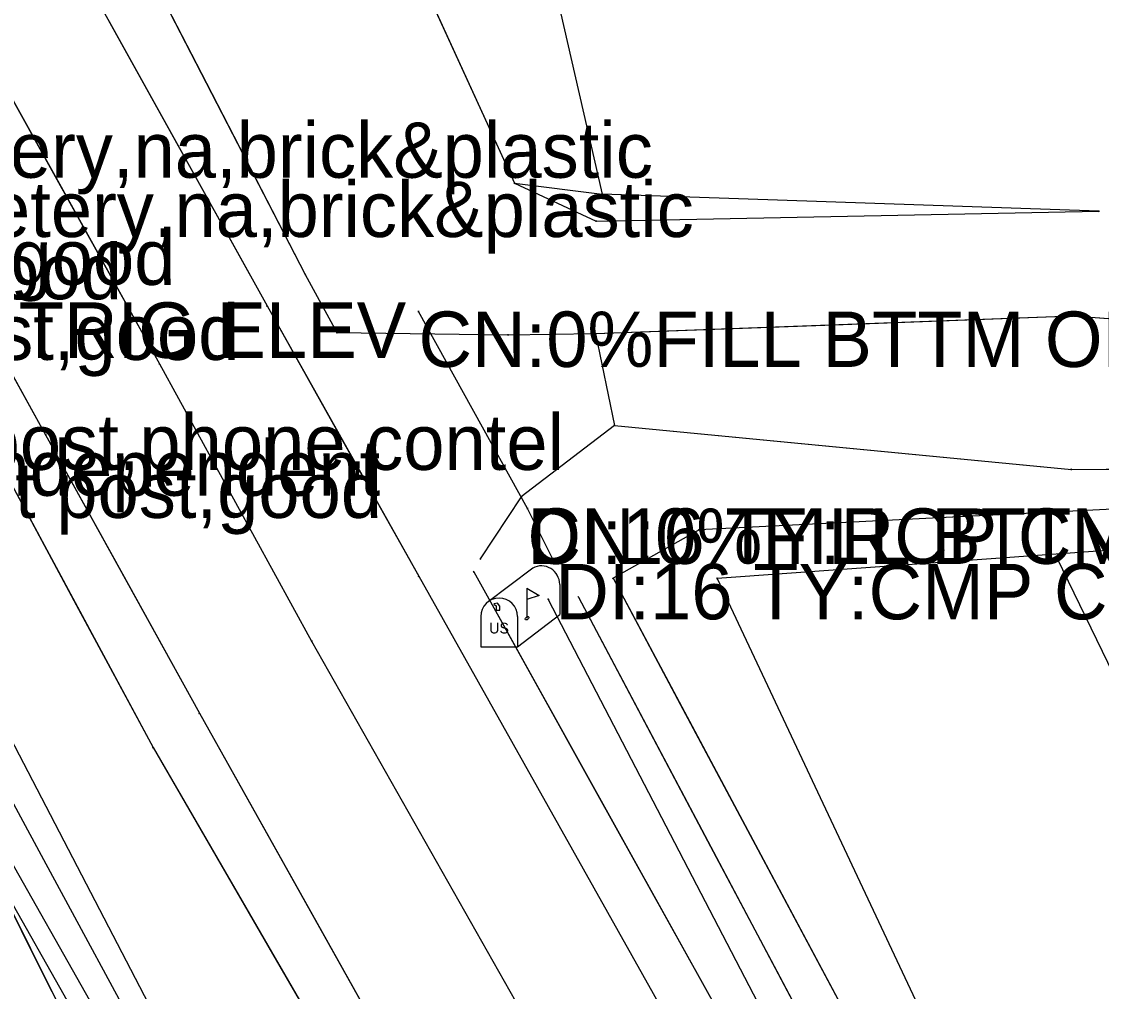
# Model space of a CAD drawing. Extents: x -99999 to 591807, y -99999 to 347168.
# Drawn here: x 589172.2 to 589269.6, y 343878.6 to 343966.1 of the extents above; entities that cross this region are included whole.
import ezdxf

# ---------------------------------------------------------------- set-up
doc = ezdxf.new("R2010")
doc.units = 0
for name, color, linetype in [('S_BREAKLINE', 7, 'Continuous'), ('S_DITCHLINE', 7, 'Continuous'), ('S_DRG_PT_SYM', 7, 'Continuous'), ('S_DRIVEWAY', 7, 'Continuous'), ('S_EDGE_BITUMINOUS', 7, 'Continuous'), ('S_EDGE_PAVEMENT', 7, 'Continuous'), ('S_FENCE', 7, 'Continuous'), ('S_FENCE_ANNOT', 7, 'Continuous'), ('S_GRD_PT_SYM', 7, 'Continuous'), ('S_MAILBOX', 7, 'Continuous'), ('S_MSC_PT_SYM', 7, 'Continuous'), ('S_PAVEMENT_CROWN', 7, 'Continuous'), ('S_RDW_PT_SYM', 7, 'Continuous'), ('S_SECONDARY_CTL_ANNOT', 7, 'Continuous'), ('S_SHOULDER', 7, 'Continuous'), ('S_SIDE_DRAIN', 7, 'Continuous'), ('S_SIDE_DRAIN_ANNOT', 7, 'Continuous'), ('S_SIGN_ANNOT', 7, 'Continuous'), ('S_TELEPHONE_UTILITIES_ANNOT', 7, 'Continuous'), ('S_UNDERGROUND_CABLE', 7, 'Continuous'), ('S_UTILITY_POLE_ANNOT', 7, 'Continuous')]:
    doc.layers.add(name, color=color, linetype=linetype)

msp = doc.modelspace()

# ---------------------------------------------------------------- linework, layer by layer
at = {"layer": 'S_BREAKLINE'}
for points in [[(589178.707, 344059.245), (589196.219, 344018.171), (589214.23, 343995.774), (589224.572, 343950.501)], [(589202.172, 343983.211), (589216.682, 343951.497)], [(589216.682, 343951.497), (589224.572, 343950.501)], [(589269.346, 343948.966), (589224.572, 343950.501)], [(589307.826, 343917.087), (589276.801, 343918.854), (589234.944, 343915.868), (589255.436, 343872.286), (589279.54, 343830.17), (589292.522, 343804.787), (589322.966, 343749.691), (589346.464, 343706.108)], [(589265.562, 343917.716), (589282.367, 343883.117), (589299.057, 343829.076), (589343.814, 343764.168), (589361.971, 343718.709)], [(589219.719, 343913.972), (589243.694, 343867.816), (589265.543, 343828.386), (589280.919, 343799.183), (589311.536, 343745.758), (589334.694, 343701.686)]]:
    msp.add_lwpolyline(points, dxfattribs=at)
at = {"layer": 'S_DITCHLINE'}
for points in [[(589292.944, 343680.411), (589286.275, 343692.355), (589279.607, 343704.3), (589272.939, 343716.245), (589266.27, 343728.189), (589258.002, 343743.462), (589249.733, 343758.735), (589241.464, 343774.007), (589233.196, 343789.28), (589223.252, 343805.716), (589213.308, 343822.151), (589203.364, 343838.587), (589193.42, 343855.022), (589183.836, 343872.755), (589174.252, 343890.487), (589164.668, 343908.22), (589155.084, 343925.952), (589144.535, 343945.213)], [(589295.448, 343681.497), (589288.727, 343693.546), (589282.007, 343705.594), (589275.286, 343717.643), (589268.565, 343729.691), (589260.423, 343745.108), (589252.281, 343760.524), (589244.139, 343775.94), (589235.997, 343791.356), (589225.751, 343807.46), (589215.504, 343823.564), (589205.258, 343839.668), (589195.011, 343855.773), (589185.737, 343873.601), (589176.463, 343891.43), (589167.19, 343909.259), (589157.916, 343927.088), (589145.699, 343945.78)], [(589307.314, 343921.098), (589276.619, 343922.409), (589233.323, 343920.25), (589225.562, 343915.881)], [(589307.314, 343921.098), (589291.967, 343921.754), (589276.619, 343922.409), (589254.971, 343921.33), (589233.323, 343920.25), (589225.562, 343915.881)], [(589225.562, 343915.881), (589249.825, 343870.459), (589271.448, 343830.318), (589284.396, 343800.855), (589316.11, 343747.232), (589340.099, 343704.207)], [(589225.562, 343915.881), (589231.628, 343904.525), (589237.694, 343893.17), (589243.759, 343881.814), (589249.825, 343870.459), (589260.637, 343850.388), (589271.448, 343830.318), (589277.922, 343815.587), (589284.396, 343800.855), (589292.324, 343787.449), (589300.253, 343774.044), (589308.181, 343760.638), (589316.11, 343747.232), (589328.104, 343725.72), (589340.099, 343704.207)], [(589222.45, 343914.182), (589246.278, 343869.207), (589268.613, 343829.634), (589282.91, 343800.448), (589312.934, 343746.223), (589336.247, 343702.575)], [(589222.45, 343914.182), (589228.407, 343902.938), (589234.364, 343891.694), (589240.321, 343880.451), (589246.278, 343869.207), (589257.445, 343849.42), (589268.613, 343829.634), (589275.761, 343815.041), (589282.91, 343800.448), (589290.416, 343786.892), (589297.922, 343773.336), (589305.428, 343759.779), (589312.934, 343746.223), (589324.591, 343724.399), (589336.247, 343702.575)]]:
    msp.add_lwpolyline(points, dxfattribs=at)
at = {"layer": 'S_DRG_PT_SYM'}
for points in [[(589208.028, 343939.931), (589208.028, 343939.981), (589208.028, 343939.931), (589207.978, 343939.931), (589208.028, 343939.931), (589208.028, 343939.881), (589208.028, 343939.931), (589208.078, 343939.931)], [(589217.839, 343922.177), (589217.839, 343922.227), (589217.839, 343922.177), (589217.789, 343922.177), (589217.839, 343922.177), (589217.839, 343922.127), (589217.839, 343922.177), (589217.889, 343922.177)], [(589217.839, 343922.177), (589217.839, 343922.227), (589217.839, 343922.177), (589217.789, 343922.177), (589217.839, 343922.177), (589217.839, 343922.127), (589217.839, 343922.177), (589217.889, 343922.177)], [(589220.361, 343917.177), (589220.361, 343917.227), (589220.361, 343917.177), (589220.311, 343917.177), (589220.361, 343917.177), (589220.361, 343917.127), (589220.361, 343917.177), (589220.411, 343917.177)]]:
    msp.add_lwpolyline(points, dxfattribs=at)
at = {"layer": 'S_DRIVEWAY'}
for points in [[(589223.97, 343937.943), (589267.021, 343939.532), (589306.29, 343936.636)], [(589223.97, 343937.943), (589245.495, 343938.737), (589267.021, 343939.532), (589286.655, 343938.084), (589306.29, 343936.636)], [(589225.702, 343929.651), (589266.882, 343925.696), (589307.69, 343926.064)], [(589225.702, 343929.651), (589246.292, 343927.673), (589266.882, 343925.696), (589287.286, 343925.88), (589307.69, 343926.064)]]:
    msp.add_lwpolyline(points, dxfattribs=at)
at = {"layer": 'S_EDGE_BITUMINOUS'}
msp.add_lwpolyline([(589200.666, 343938.024), (589216.098, 343937.819), (589223.97, 343937.943), (589225.702, 343929.651), (589217.288, 343923.216), (589213.599, 343917.633)], dxfattribs=at)
msp.add_lwpolyline([(589200.666, 343938.024), (589216.098, 343937.819), (589223.97, 343937.943), (589225.702, 343929.651), (589217.288, 343923.216), (589213.599, 343917.633)], dxfattribs=at)
at = {"layer": 'S_EDGE_PAVEMENT'}
for points in [[(589044.064, 344210.383), (589062.611, 344176.978), (589089.035, 344129.797), (589108.669, 344094.278), (589125.565, 344064.193), (589145.195, 344028.974), (589161.688, 343999.91), (589175.358, 343974.711), (589194.37, 343940.441), (589208.048, 343916.063), (589231.369, 343874.529), (589249.479, 343841.725), (589270.078, 343805.141), (589289.795, 343769.164), (589308.912, 343733.904), (589328.843, 343697.753)], [(589023.862, 344198.696), (589042.878, 344164.723), (589068.451, 344118.72), (589088.798, 344082.183), (589106.799, 344049.991), (589124.918, 344017.734), (589142.031, 343987.049), (589155.388, 343963.212), (589174.405, 343928.823), (589188.269, 343903.723), (589210.345, 343864.327), (589229.441, 343830.558), (589250.196, 343793.383), (589269.113, 343758.947), (589288.957, 343722.639), (589307.862, 343688.024)], [(589148.709, 343975.131), (589155.388, 343963.212), (589164.896, 343946.018), (589174.405, 343928.823), (589181.337, 343916.273), (589188.269, 343903.723), (589199.307, 343884.025), (589210.345, 343864.327), (589219.893, 343847.443), (589229.441, 343830.558), (589239.819, 343811.971), (589250.196, 343793.383), (589259.655, 343776.165), (589269.113, 343758.947), (589279.035, 343740.793), (589288.957, 343722.639), (589298.41, 343705.331), (589307.862, 343688.024)], [(589175.358, 343974.711), (589184.864, 343957.576), (589194.37, 343940.441), (589201.209, 343928.252), (589208.048, 343916.063), (589219.709, 343895.296), (589231.369, 343874.529), (589240.424, 343858.127), (589249.479, 343841.725), (589259.779, 343823.433), (589270.078, 343805.141), (589279.936, 343787.153), (589289.795, 343769.164), (589299.354, 343751.534), (589308.912, 343733.904), (589318.878, 343715.829), (589328.843, 343697.753)]]:
    msp.add_lwpolyline(points, dxfattribs=at)
at = {"layer": 'S_FENCE'}
for p, q in [((589202.172, 343983.211), (589216.682, 343951.497)), ((589216.682, 343951.497), (589224.037, 343948.089)), ((589224.037, 343948.089), (589269.346, 343948.966)), ((589188.108, 343852.274), (589151.217, 343926.322))]:
    msp.add_line(p, q, dxfattribs=at)
for points in [[(589202.172, 343983.211), (589216.682, 343951.497)], [(589216.682, 343951.497), (589224.037, 343948.089)], [(589224.037, 343948.089), (589269.346, 343948.966)], [(589174.979, 343878.628), (589153.096, 343922.551)]]:
    msp.add_lwpolyline(points, dxfattribs=at)
at = {"layer": 'S_GRD_PT_SYM'}
for points in [[(589216.682, 343951.497), (589216.688, 343951.547), (589216.682, 343951.497), (589216.632, 343951.504), (589216.682, 343951.497), (589216.676, 343951.448), (589216.682, 343951.497), (589216.732, 343951.491)], [(589216.682, 343951.497), (589216.727, 343951.518), (589216.682, 343951.497), (589216.661, 343951.543), (589216.682, 343951.497), (589216.637, 343951.477), (589216.682, 343951.497), (589216.703, 343951.452)], [(589224.572, 343950.501), (589224.578, 343950.551), (589224.572, 343950.501), (589224.522, 343950.508), (589224.572, 343950.501), (589224.565, 343950.452), (589224.572, 343950.501), (589224.621, 343950.495)], [(589224.572, 343950.501), (589224.57, 343950.451), (589224.572, 343950.501), (589224.622, 343950.5), (589224.572, 343950.501), (589224.573, 343950.551), (589224.572, 343950.501), (589224.522, 343950.503)], [(589224.572, 343950.501), (589224.62, 343950.513), (589224.572, 343950.501), (589224.56, 343950.55), (589224.572, 343950.501), (589224.523, 343950.49), (589224.572, 343950.501), (589224.583, 343950.453)], [(589269.346, 343948.966), (589269.346, 343949.016), (589269.346, 343948.966), (589269.296, 343948.966), (589269.346, 343948.966), (589269.346, 343948.916), (589269.346, 343948.966), (589269.396, 343948.966)], [(589269.346, 343948.966), (589269.344, 343948.916), (589269.346, 343948.966), (589269.396, 343948.965), (589269.346, 343948.966), (589269.347, 343949.016), (589269.346, 343948.966), (589269.296, 343948.968)], [(589233.323, 343920.25), (589233.348, 343920.207), (589233.323, 343920.25), (589233.367, 343920.275), (589233.323, 343920.25), (589233.299, 343920.294), (589233.323, 343920.25), (589233.28, 343920.226)], [(589265.562, 343917.716), (589265.607, 343917.738), (589265.562, 343917.716), (589265.541, 343917.761), (589265.562, 343917.716), (589265.518, 343917.694), (589265.562, 343917.716), (589265.584, 343917.671)], [(589225.562, 343915.881), (589225.606, 343915.905), (589225.562, 343915.881), (589225.538, 343915.925), (589225.562, 343915.881), (589225.518, 343915.857), (589225.562, 343915.881), (589225.585, 343915.837)], [(589225.562, 343915.881), (589225.586, 343915.837), (589225.562, 343915.881), (589225.605, 343915.906), (589225.562, 343915.881), (589225.537, 343915.925), (589225.562, 343915.881), (589225.518, 343915.856)], [(589234.944, 343915.868), (589234.99, 343915.889), (589234.944, 343915.868), (589234.923, 343915.913), (589234.944, 343915.868), (589234.899, 343915.847), (589234.944, 343915.868), (589234.966, 343915.823)], [(589219.719, 343913.972), (589219.764, 343913.995), (589219.719, 343913.972), (589219.696, 343914.016), (589219.719, 343913.972), (589219.675, 343913.949), (589219.719, 343913.972), (589219.742, 343913.927)], [(589222.45, 343914.182), (589222.495, 343914.205), (589222.45, 343914.182), (589222.427, 343914.226), (589222.45, 343914.182), (589222.406, 343914.158), (589222.45, 343914.182), (589222.474, 343914.138)]]:
    msp.add_lwpolyline(points, close=True, dxfattribs=at)
at = {"layer": 'S_MAILBOX'}
for p, q in [((589214.188, 343913.696), (589218.322, 343916.805)), ((589217.803, 343914.985), (589217.803, 343912.27)), ((589220.754, 343915.331), (589220.754, 343912.616)), ((589213.634, 343912.422), (589213.634, 343909.707)), ((589216.958, 343909.707), (589220.754, 343912.616)), ((589216.958, 343912.422), (589216.958, 343909.707)), ((589213.634, 343909.707), (589216.958, 343909.707))]:
    msp.add_line(p, q, dxfattribs=at)
for points in [[(589217.803, 343914.985), (589218.911, 343914.32), (589217.803, 343913.974)], [(589214.818, 343913.537), (589215.04, 343913.399), (589215.04, 343913.011), (589215.344, 343913.011), (589215.344, 343913.371), (589215.15, 343913.62), (589214.818, 343913.565)]]:
    msp.add_lwpolyline(points, dxfattribs=at)
for centre, end in [((589219.091, 343915.331), 117.57184), ((589215.296, 343912.422), 180)]:
    msp.add_arc(centre, 1.662, 0, end, dxfattribs=at)
msp.add_ellipse((589217.803, 343912.27), major_axis=(0.145, 0.132), ratio=0.564646, dxfattribs=at)
at = {"layer": 'S_MSC_PT_SYM'}
for points in [[(589216.682, 343951.497), (589216.682, 343951.547), (589216.682, 343951.497), (589216.632, 343951.497), (589216.682, 343951.497), (589216.682, 343951.448), (589216.682, 343951.497), (589216.732, 343951.497)], [(589269.346, 343948.966), (589269.346, 343949.016), (589269.346, 343948.966), (589269.296, 343948.966), (589269.346, 343948.966), (589269.346, 343948.916), (589269.346, 343948.966), (589269.396, 343948.966)], [(589224.037, 343948.089), (589224.037, 343948.139), (589224.037, 343948.089), (589223.987, 343948.089), (589224.037, 343948.089), (589224.037, 343948.039), (589224.037, 343948.089), (589224.087, 343948.089)]]:
    msp.add_lwpolyline(points, dxfattribs=at)
at = {"layer": 'S_PAVEMENT_CROWN'}
for points in [[(589034.182, 344204.283), (589052.821, 344171.662), (589078.888, 344124.449), (589099.084, 344088.667), (589116.35, 344057.605), (589135.374, 344023.693), (589152.412, 343993.377), (589165.895, 343968.999), (589184.661, 343935.227), (589198.392, 343910.199), (589220.861, 343870.523), (589240.038, 343836.277), (589260.161, 343799.879), (589280.047, 343763.839), (589299.46, 343728.427), (589318.911, 343692.885)], [(589165.895, 343968.999), (589175.278, 343952.113), (589184.661, 343935.227), (589191.526, 343922.713), (589198.392, 343910.199), (589209.627, 343890.361), (589220.861, 343870.523), (589230.449, 343853.4), (589240.038, 343836.277), (589250.099, 343818.078), (589260.161, 343799.879), (589270.104, 343781.859), (589280.047, 343763.839), (589289.754, 343746.133), (589299.46, 343728.427), (589309.185, 343710.656), (589318.911, 343692.885)]]:
    msp.add_lwpolyline(points, dxfattribs=at)
at = {"layer": 'S_RDW_PT_SYM'}
for points in [[(589197.81, 343943.256), (589197.854, 343943.28), (589197.81, 343943.256), (589197.786, 343943.3), (589197.81, 343943.256), (589197.766, 343943.232), (589197.81, 343943.256), (589197.834, 343943.212)], [(589194.37, 343940.441), (589194.414, 343940.465), (589194.37, 343940.441), (589194.346, 343940.484), (589194.37, 343940.441), (589194.327, 343940.416), (589194.37, 343940.441), (589194.395, 343940.397)], [(589267.021, 343939.532), (589267.024, 343939.581), (589267.021, 343939.532), (589266.971, 343939.535), (589267.021, 343939.532), (589267.017, 343939.482), (589267.021, 343939.532), (589267.07, 343939.528)], [(589200.666, 343938.024), (589200.667, 343938.073), (589200.666, 343938.024), (589200.616, 343938.024), (589200.666, 343938.024), (589200.665, 343937.974), (589200.666, 343938.024), (589200.716, 343938.023)], [(589200.666, 343938.024), (589200.71, 343938.047), (589200.666, 343938.024), (589200.642, 343938.067), (589200.666, 343938.024), (589200.622, 343938), (589200.666, 343938.024), (589200.69, 343937.98)], [(589216.098, 343937.819), (589216.097, 343937.869), (589216.098, 343937.819), (589216.048, 343937.819), (589216.098, 343937.819), (589216.099, 343937.77), (589216.098, 343937.819), (589216.148, 343937.82)], [(589223.97, 343937.943), (589223.968, 343937.992), (589223.97, 343937.943), (589223.92, 343937.941), (589223.97, 343937.943), (589223.971, 343937.893), (589223.97, 343937.943), (589224.02, 343937.944)], [(589223.97, 343937.943), (589224.019, 343937.953), (589223.97, 343937.943), (589223.959, 343937.991), (589223.97, 343937.943), (589223.921, 343937.932), (589223.97, 343937.943), (589223.98, 343937.894)], [(589184.661, 343935.227), (589184.705, 343935.251), (589184.661, 343935.227), (589184.637, 343935.271), (589184.661, 343935.227), (589184.617, 343935.203), (589184.661, 343935.227), (589184.685, 343935.183)], [(589225.702, 343929.651), (589225.706, 343929.701), (589225.702, 343929.651), (589225.652, 343929.656), (589225.702, 343929.651), (589225.697, 343929.601), (589225.702, 343929.651), (589225.751, 343929.646)], [(589225.702, 343929.651), (589225.732, 343929.611), (589225.702, 343929.651), (589225.741, 343929.681), (589225.702, 343929.651), (589225.671, 343929.691), (589225.702, 343929.651), (589225.662, 343929.621)], [(589174.405, 343928.823), (589174.449, 343928.847), (589174.405, 343928.823), (589174.381, 343928.867), (589174.405, 343928.823), (589174.361, 343928.799), (589174.405, 343928.823), (589174.429, 343928.779)], [(589266.882, 343925.696), (589266.881, 343925.746), (589266.882, 343925.696), (589266.832, 343925.695), (589266.882, 343925.696), (589266.882, 343925.646), (589266.882, 343925.696), (589266.931, 343925.696)], [(589217.288, 343923.216), (589217.33, 343923.189), (589217.288, 343923.216), (589217.316, 343923.258), (589217.288, 343923.216), (589217.246, 343923.244), (589217.288, 343923.216), (589217.261, 343923.175)], [(589213.599, 343917.633), (589213.641, 343917.606), (589213.599, 343917.633), (589213.626, 343917.675), (589213.599, 343917.633), (589213.557, 343917.661), (589213.599, 343917.633), (589213.571, 343917.591)], [(589208.048, 343916.063), (589208.092, 343916.087), (589208.048, 343916.063), (589208.024, 343916.107), (589208.048, 343916.063), (589208.005, 343916.039), (589208.048, 343916.063), (589208.073, 343916.019)], [(589213.012, 343916.474), (589213.056, 343916.498), (589213.012, 343916.474), (589212.988, 343916.518), (589213.012, 343916.474), (589212.968, 343916.45), (589213.012, 343916.474), (589213.036, 343916.43)], [(589198.392, 343910.199), (589198.435, 343910.223), (589198.392, 343910.199), (589198.367, 343910.242), (589198.392, 343910.199), (589198.348, 343910.174), (589198.392, 343910.199), (589198.416, 343910.155)], [(589188.269, 343903.723), (589188.313, 343903.748), (589188.269, 343903.723), (589188.245, 343903.767), (589188.269, 343903.723), (589188.225, 343903.699), (589188.269, 343903.723), (589188.294, 343903.679)], [(589184.1, 343900.609), (589184.143, 343900.634), (589184.1, 343900.609), (589184.075, 343900.652), (589184.1, 343900.609), (589184.057, 343900.584), (589184.1, 343900.609), (589184.125, 343900.566)]]:
    msp.add_lwpolyline(points, close=True, dxfattribs=at)
at = {"layer": 'S_SHOULDER'}
for points in [[(589179.992, 343977.813), (589197.81, 343943.256), (589200.666, 343938.024)], [(589179.992, 343977.813), (589188.901, 343960.535), (589197.81, 343943.256), (589200.666, 343938.024)], [(589150.569, 343960.495), (589170.208, 343926.38), (589184.1, 343900.609), (589206.302, 343862.261), (589224.954, 343827.94), (589245.985, 343790.869), (589265.2, 343757.033), (589284.286, 343720.227), (589303.787, 343685.692)], [(589150.569, 343960.495), (589160.389, 343943.437), (589170.208, 343926.38), (589177.154, 343913.494), (589184.1, 343900.609), (589195.201, 343881.435), (589206.302, 343862.261), (589215.628, 343845.101), (589224.954, 343827.94), (589235.469, 343809.405), (589245.985, 343790.869), (589255.593, 343773.951), (589265.2, 343757.033), (589274.743, 343738.63), (589284.286, 343720.227), (589294.036, 343702.96), (589303.787, 343685.692)], [(589213.012, 343916.474), (589235.093, 343876.73), (589253.896, 343844.328), (589274.011, 343807.366), (589294.287, 343771.453), (589313.174, 343736.4), (589332.935, 343700.867)], [(589213.012, 343916.474), (589224.053, 343896.602), (589235.093, 343876.73), (589244.494, 343860.529), (589253.896, 343844.328), (589263.953, 343825.847), (589274.011, 343807.366), (589284.149, 343789.41), (589294.287, 343771.453), (589303.73, 343753.927), (589313.174, 343736.4), (589323.054, 343718.634), (589332.935, 343700.867)]]:
    msp.add_lwpolyline(points, dxfattribs=at)
at = {"layer": 'S_SIDE_DRAIN'}
for p, q in [((589217.839, 343922.177), (589208.028, 343939.931)), ((589220.361, 343917.177), (589217.839, 343922.177))]:
    msp.add_line(p, q, dxfattribs=at)
at = {"layer": 'S_UNDERGROUND_CABLE'}
for p, q in [((589227.156, 343791.77), (589149.153, 343929.406)), ((589225.508, 343790.96), (589147.378, 343928.994))]:
    msp.add_line(p, q, dxfattribs=at)

# ---------------------------------------------------------------- texts
at = {"layer": 'S_FENCE_ANNOT'}
for s, p in [('6 brb st post,good', (589132.592, 343942.329)), ("4' chain link,good", (589129.834, 343941.037)), ('6 brb st post,good', (589138.36, 343935.567)), ('6 brb st post,good', (589151.217, 343921.322))]:
    msp.add_text(s, height=5, dxfattribs=at).set_placement(p)
at = {"layer": 'S_MAILBOX'}
msp.add_text('US', height=0.96, rotation=360, dxfattribs=at).set_placement((589214.397, 343910.901))
at = {"layer": 'S_SECONDARY_CTL_ANNOT'}
msp.add_text('PD:8 SPK,TRIG ELEV', height=5, dxfattribs=at).set_placement((589140.03, 343935.751))
at = {"layer": 'S_SIDE_DRAIN_ANNOT'}
for s, p in [('CN:0%FILL BTTM OF PIPE', (589208.028, 343934.931)), ('CN:0%FILL BTTM OF PIPE', (589217.839, 343917.177)), ('DI:16 TY:RCP CN:0%FILL BTTM OF ', (589217.839, 343917.177)), ('DI:16 TY:CMP CN:15%FILL BTTM OF', (589220.361, 343912.177))]:
    msp.add_text(s, height=5, dxfattribs=at).set_placement(p)
at = {"layer": 'S_SIGN_ANNOT'}
for p in [(589121.019, 343951.992), (589124.708, 343946.649)]:
    msp.add_text('white bluff cemetery,na,brick&plastic', height=5, dxfattribs=at).set_placement(p)
at = {"layer": 'S_TELEPHONE_UTILITIES_ANNOT'}
msp.add_text('phone,independent', height=5, dxfattribs=at).set_placement((589147.32, 343923.318))
at = {"layer": 'S_UTILITY_POLE_ANNOT'}
msp.add_text('wood post,phone,contel', height=5, dxfattribs=at).set_placement((589150.521, 343925.65))

doc.saveas('drawing.dxf')
